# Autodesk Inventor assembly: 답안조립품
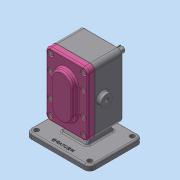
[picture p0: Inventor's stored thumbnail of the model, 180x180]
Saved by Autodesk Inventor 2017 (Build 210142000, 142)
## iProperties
Part Number: 답안조립품
Material: 일반
Document SubType Name: Assembly
Designer: MRC
Author: MRC
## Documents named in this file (11)
- C:\Users\MRC\Desktop\700407V1051\답안조립품.iam
- C:\Users\MRC\Desktop\700407V1051\본체.ipt
- C:\Users\MRC\Desktop\700407V1051\Ű 6 x 6 x 18.ipt
- C:\Users\MRC\Desktop\700407V1051\개스킷.ipt
- C:\Users\MRC\Desktop\700407V1051\메인축.ipt
- C:\Users\MRC\Desktop\700407V1051\베어링부시.ipt
- C:\Users\MRC\Desktop\700407V1051\볼트 M5.ipt
- C:\Users\MRC\Desktop\700407V1051\서브축.ipt
- C:\Users\MRC\Desktop\700407V1051\스퍼기어.ipt
- C:\Users\MRC\Desktop\700407V1051\오일 실 16 28 7.ipt
- C:\Users\MRC\Desktop\700407V1051\커버.ipt
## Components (3 placed, 2 different names)
1. Ű 6 x 6 x 18:1
2. Ű 6 x 6 x 18:2
3. 개스킷:2
